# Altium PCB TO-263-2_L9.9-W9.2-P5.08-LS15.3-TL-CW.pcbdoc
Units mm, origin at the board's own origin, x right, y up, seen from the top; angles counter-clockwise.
Board outline 29.37 x 22.9 mm, 2 copper layers (Top Layer, Bottom Layer), stack 0 mm thick; 1 components, 0 nets, 3 pads, 0 vias.
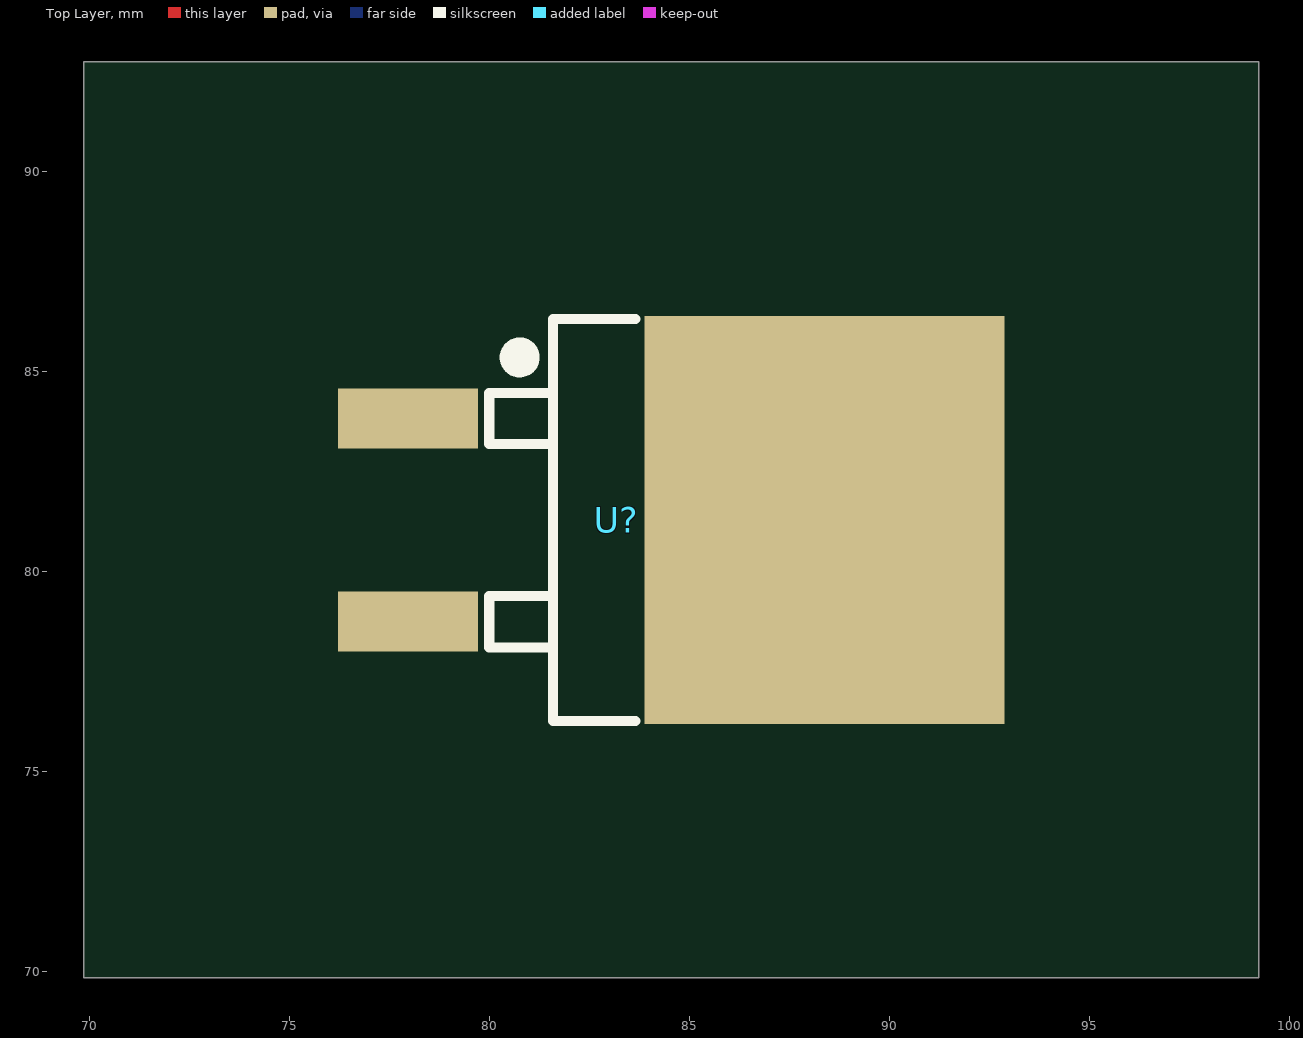
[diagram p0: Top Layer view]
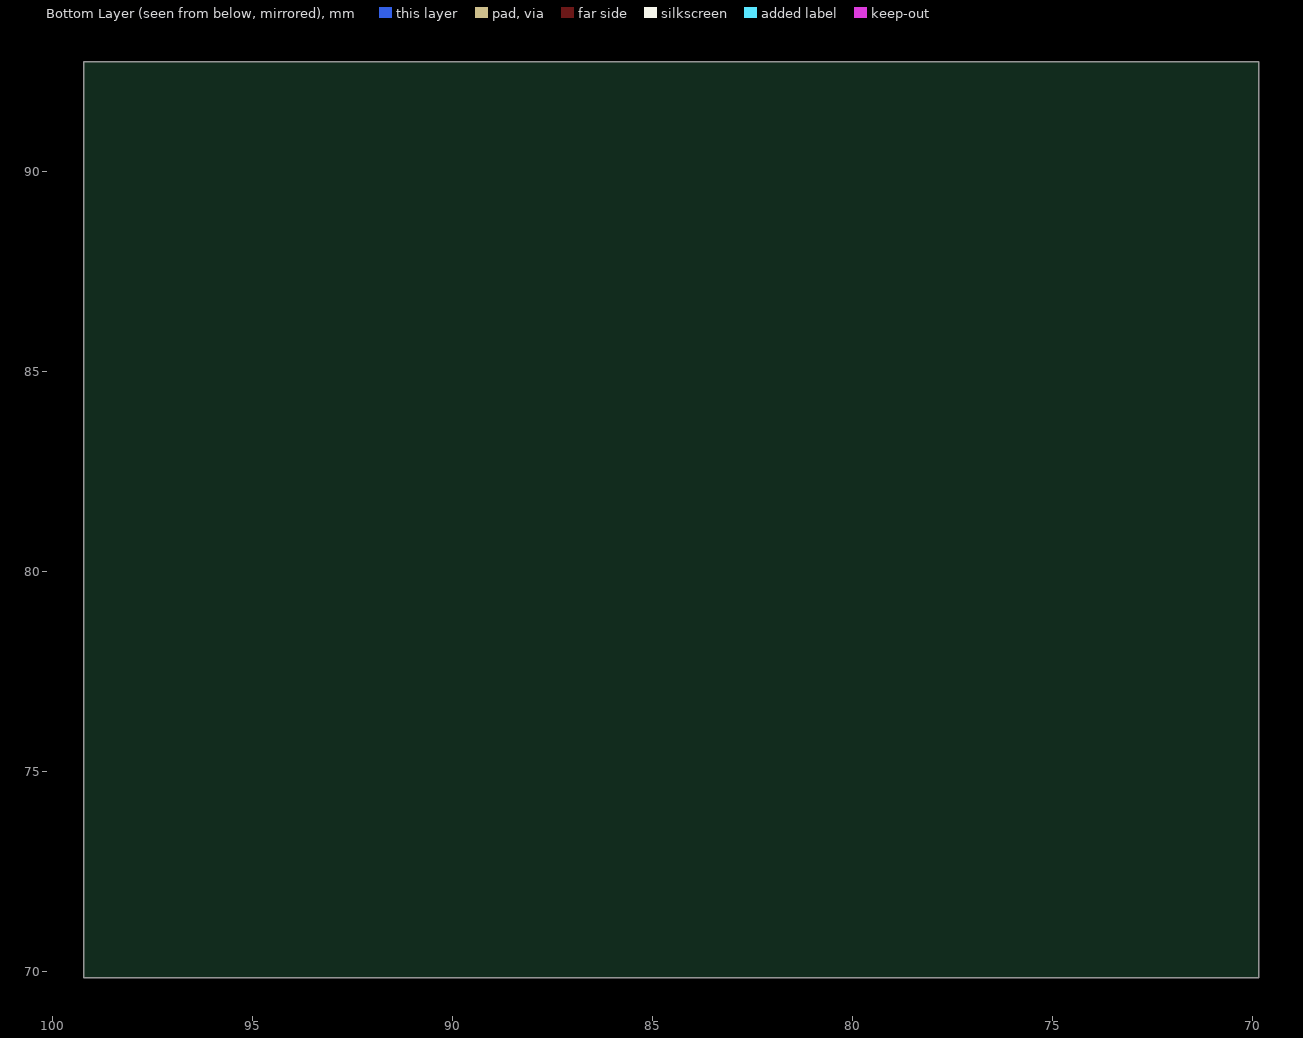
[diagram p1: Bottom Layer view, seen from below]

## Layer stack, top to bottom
Top Layer: signal copper (thickness not stored)
Bottom Layer: signal copper (thickness not stored)

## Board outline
99.219,69.85 69.85,69.85 69.85,92.75 99.219,92.75

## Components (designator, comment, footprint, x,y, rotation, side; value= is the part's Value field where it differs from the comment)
U? "" TO-263-2_L9.9-W9.2-P5.08-LS15.3-TL-CW 83.159,81.3 r0 top

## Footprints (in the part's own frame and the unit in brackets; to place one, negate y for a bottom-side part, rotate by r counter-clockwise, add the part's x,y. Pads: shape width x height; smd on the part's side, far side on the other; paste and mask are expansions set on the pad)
TO-263-2_L9.9-W9.2-P5.08-LS15.3-TL-CW [mm]
  rect 3.5x1.5 smd: 1(-5.209,2.54) 3(-5.209,-2.54)
  rect 9x10.2 smd: 2(5.209,0)
  silkscreen extent -3.18,-5.03 0.47,5.03

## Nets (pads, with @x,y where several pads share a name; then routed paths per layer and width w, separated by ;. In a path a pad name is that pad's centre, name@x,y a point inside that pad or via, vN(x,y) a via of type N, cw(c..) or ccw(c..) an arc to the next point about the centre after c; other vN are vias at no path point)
pads on no net: U?.1 U?.2 U?.3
